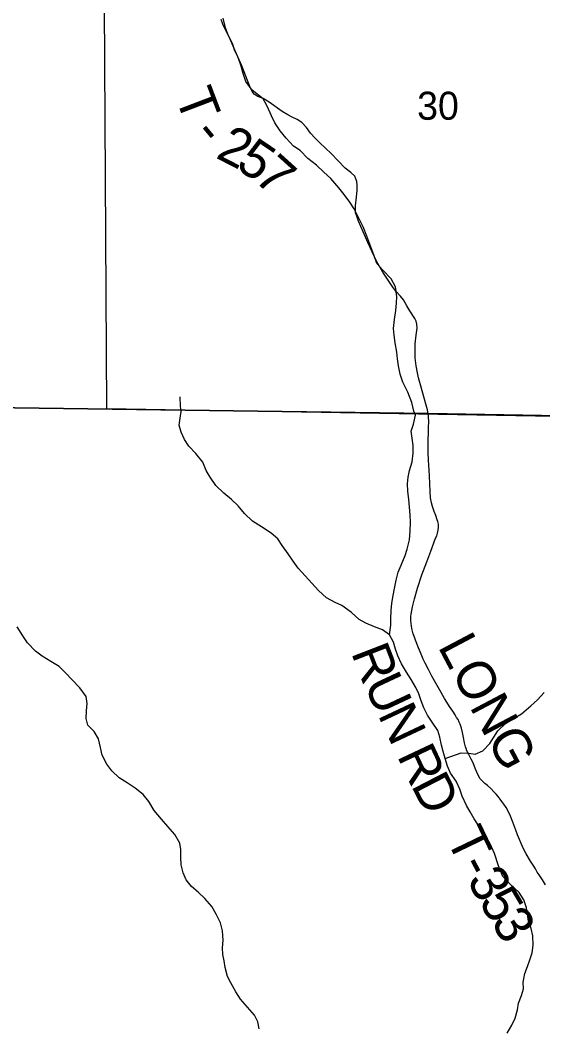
# Model space of a CAD drawing. Extents: x 0 to 34, y -8.9 to 22.
# Drawn here: x 28.944 to 29.724, y 15.866 to 17.37 of the extents above; entities that cross this region are included whole.
import ezdxf

# ---------------------------------------------------------------- set-up
doc = ezdxf.new("R2010")
doc.units = 0
for name, color, linetype in [('GM_X_Corporation', 7, 'Continuous'), ('GM_X_Minor_River', 7, 'Continuous'), ('GM_X_Section_Text', 7, 'Continuous'), ('GM_X_Township_Road', 7, 'Continuous'), ('GM_X_Township_Road_Text', 7, 'Continuous')]:
    doc.layers.add(name, color=color, linetype=linetype)

msp = doc.modelspace()

# ---------------------------------------------------------------- linework, layer by layer
at = {"layer": 'GM_X_Corporation'}
for points in [[(28.3182, 16.8002), (29.5528, 16.7835), (30.4571, 16.7673), (30.5167, 16.7663), (30.5167, 21.4), (23.7167, 21.4)], [(23.7167, 14.6), (30.5167, 14.6), (30.5167, 16.7663), (30.4571, 16.7673), (29.5528, 16.7835), (28.3182, 16.8002)]]:
    msp.add_lwpolyline(points, dxfattribs=at)
for points in [[(30.5167, 16.7663), (30.5167, 21.4), (28.2203, 21.4), (28.2198, 21.3092), (28.2124, 18.7899), (28.2124, 18.7889), (28.2011, 18.1006), (28.201, 18.0921), (28.1882, 17.3108), (28.1928, 16.8054), (28.3182, 16.8002), (29.5528, 16.7835), (30.4571, 16.7673)], [(30.0751, 17.7225), (30.0622, 16.7735), (29.0733, 16.7902), (29.0677, 17.7366)], [(28.1739, 14.6), (30.5167, 14.6), (30.5167, 16.7663), (30.4571, 16.7673), (29.5528, 16.7835), (28.3182, 16.8002), (28.1928, 16.8054), (28.1817, 16.6637), (28.1846, 16.3341), (28.1918, 16.1509), (28.1809, 15.2987)]]:
    msp.add_lwpolyline(points, close=True, dxfattribs=at)
at = {"layer": 'GM_X_Minor_River'}
for points in [[(29.5343, 16.7806), (29.5315, 16.7867), (29.5286, 16.7996), (29.5224, 16.8151), (29.515, 16.8302), (29.5114, 16.8419), (29.5089, 16.8544), (29.5073, 16.8646), (29.506, 16.8749), (29.5036, 16.8889), (29.5023, 16.8999), (29.501, 16.9101), (29.5027, 16.9234), (29.5048, 16.9371), (29.5058, 16.9478), (29.5061, 16.958), (29.5044, 16.9724), (29.4978, 16.9841), (29.4854, 16.9972), (29.4766, 17.007), (29.4719, 17.0199), (29.4616, 17.0478), (29.4561, 17.0614), (29.4491, 17.0754), (29.4425, 17.0886), (29.4359, 17.0984), (29.4274, 17.11), (29.4197, 17.1198), (29.4078, 17.1337), (29.397, 17.1431), (29.3863, 17.1536), (29.3732, 17.1636), (29.3621, 17.1753), (29.3521, 17.182), (29.341, 17.194), (29.3321, 17.2049), (29.3243, 17.2169), (29.3189, 17.2271), (29.3126, 17.2415), (29.3064, 17.2524), (29.2903, 17.2655), (29.281, 17.2786), (29.2767, 17.2904), (29.2739, 17.301), (29.2692, 17.3142), (29.2645, 17.324), (29.261, 17.335), (29.2551, 17.3463), (29.2504, 17.3584), (29.2468, 17.3727)], [(29.184, 16.7862), (29.1831, 16.7944), (29.1825, 16.808)], [(29.6711, 15.8591), (29.6777, 15.871), (29.6827, 15.8814), (29.6863, 15.8938), (29.6879, 15.9037), (29.6925, 15.9153), (29.6953, 15.9254), (29.6949, 15.9353), (29.6974, 15.9481), (29.7012, 15.9586), (29.7047, 15.9684), (29.7082, 15.9789), (29.7098, 15.9902), (29.7093, 16.0043), (29.7067, 16.0151), (29.703, 16.0263), (29.7015, 16.0366), (29.6996, 16.0462), (29.696, 16.0582), (29.6888, 16.0691), (29.6753, 16.0815), (29.6643, 16.0926), (29.6582, 16.1089), (29.6521, 16.127), (29.6458, 16.1417), (29.638, 16.1543), (29.6215, 16.1786), (29.6155, 16.1891), (29.6102, 16.1988), (29.6036, 16.2128), (29.6002, 16.2229), (29.5946, 16.2349), (29.5864, 16.2467), (29.5819, 16.2571), (29.5782, 16.2687), (29.5752, 16.2791), (29.5729, 16.2887), (29.5704, 16.3006), (29.5674, 16.3103), (29.5588, 16.3232), (29.552, 16.3334), (29.5464, 16.3443), (29.5426, 16.3547), (29.5389, 16.3651), (29.5344, 16.3748), (29.5276, 16.3865), (29.5205, 16.3975), (29.513, 16.41), (29.5078, 16.422), (29.5041, 16.4317), (29.5011, 16.4421), (29.4951, 16.453), (29.4847, 16.4607), (29.4727, 16.465), (29.46, 16.4705), (29.45, 16.4763), (29.4386, 16.4863), (29.4242, 16.4968), (29.4142, 16.5014), (29.4011, 16.5084), (29.3894, 16.5192), (29.3691, 16.5414), (29.3589, 16.5528), (29.3513, 16.5631), (29.3438, 16.574), (29.3352, 16.5862), (29.3284, 16.5964), (29.3185, 16.6048), (29.304, 16.6142), (29.2907, 16.6227), (29.279, 16.6339), (29.2692, 16.6454), (29.2593, 16.6549), (29.248, 16.6645), (29.2359, 16.6757), (29.2273, 16.6883), (29.2216, 16.6984), (29.2164, 16.7108), (29.2063, 16.7238), (29.1958, 16.7345), (29.1893, 16.7443), (29.1841, 16.7555), (29.1811, 16.7659), (29.1825, 16.7763), (29.184, 16.7862)], [(29.4951, 16.453), (29.4972, 16.4674), (29.4972, 16.4769), (29.4977, 16.4894), (29.499, 16.5004), (29.5006, 16.5121), (29.5026, 16.5223), (29.505, 16.5347), (29.5082, 16.5468), (29.5128, 16.5572), (29.5187, 16.5714), (29.5218, 16.5812), (29.5251, 16.5951), (29.526, 16.6076), (29.5266, 16.6213), (29.5263, 16.632), (29.5252, 16.6438), (29.5242, 16.6549), (29.5228, 16.6675), (29.5221, 16.6782), (29.5229, 16.6881), (29.5253, 16.6982), (29.5289, 16.7114), (29.5305, 16.7242), (29.5307, 16.7357), (29.5292, 16.7467), (29.5274, 16.7567), (29.5312, 16.7676), (29.5343, 16.7806)], [(29.3008, 15.8656), (29.2986, 15.8763), (29.2937, 15.8861), (29.2831, 15.8979), (29.273, 15.9098), (29.2658, 15.9207), (29.2584, 15.934), (29.2535, 15.9437), (29.2499, 15.9572), (29.2484, 15.9668), (29.2465, 15.9764), (29.2458, 15.9863), (29.2467, 15.998), (29.2461, 16.0118), (29.2428, 16.0237), (29.2365, 16.0365), (29.2302, 16.0482), (29.2196, 16.0601), (29.2094, 16.0693), (29.1998, 16.0777), (29.1919, 16.0879), (29.187, 16.0984), (29.1841, 16.1103), (29.1838, 16.1217), (29.1839, 16.1332), (29.1824, 16.1427), (29.1746, 16.1552), (29.1645, 16.1675), (29.155, 16.1782), (29.1438, 16.1912), (29.136, 16.2045), (29.1273, 16.2151), (29.1155, 16.2244), (29.1037, 16.2325), (29.0918, 16.2398), (29.0805, 16.2506), (29.0733, 16.2604), (29.0662, 16.2737), (29.0637, 16.2852), (29.0608, 16.2979), (29.0544, 16.3088), (29.0449, 16.3183), (29.0423, 16.3283), (29.0428, 16.3401), (29.0436, 16.3507), (29.0422, 16.3611), (29.0328, 16.374), (29.0208, 16.3867), (29.0121, 16.3962), (29.0018, 16.4058), (28.9896, 16.4132), (28.9766, 16.4213), (28.9667, 16.429), (28.9546, 16.4413), (28.9478, 16.4515), (28.9393, 16.4652)], [(29.5782, 16.2687), (29.6021, 16.2772), (29.6135, 16.2767), (29.6234, 16.2751), (29.6346, 16.2803), (29.645, 16.2909), (29.6572, 16.3102), (29.6687, 16.3211), (29.6816, 16.3289), (29.6925, 16.3353), (29.7063, 16.3472), (29.7162, 16.3563), (29.7262, 16.3673)]]:
    msp.add_lwpolyline(points, dxfattribs=at)
at = {"layer": 'GM_X_Township_Road'}
for points in [[(29.553, 16.783), (29.5519, 16.7887), (29.5491, 16.799), (29.5426, 16.8225), (29.5386, 16.8367), (29.5372, 16.8439), (29.5351, 16.8542), (29.5335, 16.8663), (29.5337, 16.8873), (29.5351, 16.9002), (29.5368, 16.9106), (29.5362, 16.9164), (29.5352, 16.9209), (29.5332, 16.9251), (29.5258, 16.9365), (29.5213, 16.9438), (29.5161, 16.9527), (29.5116, 16.9584), (29.5047, 16.9657), (29.5, 16.9717), (29.4853, 16.9938), (29.4758, 17.0106), (29.4629, 17.0383), (29.449, 17.0702), (29.4463, 17.0776), (29.4445, 17.0832), (29.4443, 17.0881), (29.4444, 17.0932), (29.4459, 17.1061), (29.4468, 17.1165), (29.4469, 17.1239), (29.4465, 17.1295), (29.4433, 17.1371), (29.4377, 17.1426), (29.4292, 17.1493), (29.408, 17.1712), (29.3912, 17.187), (29.3842, 17.194), (29.3775, 17.2013), (29.3712, 17.2098), (29.3645, 17.2174), (29.3576, 17.2215), (29.35, 17.225), (29.3435, 17.2285), (29.335, 17.2337), (29.3155, 17.2476), (29.3064, 17.2532), (29.2987, 17.2562), (29.2933, 17.2593), (29.29, 17.2635), (29.2869, 17.2709), (29.2746, 17.3018), (29.2648, 17.3243), (29.2557, 17.3448), (29.2496, 17.3573), (29.2463, 17.3639), (29.2439, 17.3706)], [(29.7282, 16.0802), (29.7236, 16.088), (29.7189, 16.0953), (29.716, 16.0995), (29.7131, 16.104), (29.7096, 16.1097), (29.7059, 16.1156), (29.6995, 16.1268), (29.6964, 16.1323), (29.6941, 16.1373), (29.6918, 16.1419), (29.6892, 16.148), (29.6866, 16.1549), (29.6838, 16.1619), (29.6792, 16.1738), (29.6757, 16.1828), (29.6724, 16.1901), (29.6693, 16.1955), (29.666, 16.2006), (29.6629, 16.2046), (29.6604, 16.2081), (29.6574, 16.2121), (29.6545, 16.2155), (29.6518, 16.2187), (29.6465, 16.2239), (29.6414, 16.2284), (29.6375, 16.2315), (29.6335, 16.2353), (29.6308, 16.2387), (29.6282, 16.2429), (29.6256, 16.2484), (29.6236, 16.253), (29.6217, 16.2582), (29.6197, 16.2632), (29.6174, 16.2678), (29.6154, 16.2718), (29.6135, 16.2748), (29.6108, 16.2804), (29.6096, 16.2836), (29.6087, 16.2862), (29.6071, 16.2922), (29.606, 16.2999), (29.6045, 16.3075), (29.6028, 16.3141), (29.6007, 16.32), (29.5994, 16.3229), (29.5976, 16.3267), (29.5955, 16.33), (29.5935, 16.3337), (29.5896, 16.3393), (29.5847, 16.3465), (29.5809, 16.3526), (29.5774, 16.3582), (29.5724, 16.3671), (29.5643, 16.3813), (29.5585, 16.3916), (29.5533, 16.4014), (29.5486, 16.4109), (29.5457, 16.4169), (29.5426, 16.4245), (29.5384, 16.4337), (29.5341, 16.4452), (29.5324, 16.4496), (29.5308, 16.4546), (29.5294, 16.4587), (29.5286, 16.4624), (29.5279, 16.4664), (29.5275, 16.4697), (29.5271, 16.4756), (29.5273, 16.4809), (29.5278, 16.4842), (29.5284, 16.4894), (29.5297, 16.495), (29.5325, 16.5071), (29.537, 16.5226), (29.5437, 16.5426), (29.5508, 16.5623), (29.5568, 16.5782), (29.5642, 16.5973), (29.5657, 16.6009), (29.5669, 16.6048), (29.5678, 16.6091), (29.5684, 16.614), (29.5683, 16.6184), (29.5676, 16.622), (29.5666, 16.6249), (29.5643, 16.631), (29.562, 16.637), (29.5593, 16.6446), (29.5579, 16.65), (29.5566, 16.6573), (29.5558, 16.6672), (29.5554, 16.679), (29.555, 16.6898), (29.5547, 16.6989), (29.5536, 16.7137), (29.5532, 16.7249), (29.5532, 16.7367), (29.5532, 16.7446), (29.5534, 16.754), (29.5537, 16.7638), (29.5538, 16.7701), (29.5535, 16.7791), (29.553, 16.783)]]:
    msp.add_lwpolyline(points, dxfattribs=at)

# ---------------------------------------------------------------- texts
at = {"layer": 'GM_X_Section_Text'}
msp.add_text('30', height=0.04186, rotation=0, dxfattribs=at).set_placement((29.5365, 17.2213))
at = {"layer": 'GM_X_Township_Road_Text'}
for s, height, rotation, p in [('T', 0.0568, 290.8575, (29.1746, 17.2561)), ('-', 0.0568, 309.7066, (29.2, 17.1989)), ('2', 0.0568, 332.789, (29.2342, 17.1654)), ('5', 0.0568, 325.8394, (29.2638, 17.1503)), ('7', 0.0568, 317.9451, (29.2911, 17.132)), ('LONG', 0.05682, 297.8588, (29.5668, 16.436)), ('R', 0.0568, 291.1549, (29.4375, 16.427)), ('U', 0.0568, 295.1026, (29.456, 16.3796)), ('N', 0.0568, 295.1561, (29.4772, 16.3343)), ('R', 0.0568, 295.217, (29.5059, 16.2731)), ('D', 0.0568, 297.3139, (29.5268, 16.2289)), ('T', 0.0568, 295.7198, (29.5791, 16.1499)), ('-', 0.0568, 297.4802, (29.5984, 16.11)), ('3', 0.0568, 299.0879, (29.61, 16.0877)), ('5', 0.0568, 300.4226, (29.6278, 16.0559)), ('3', 0.0568, 301.1229, (29.6459, 16.0251))]:
    msp.add_text(s, height=height, rotation=rotation, dxfattribs=at).set_placement(p)

doc.saveas('drawing.dxf')
